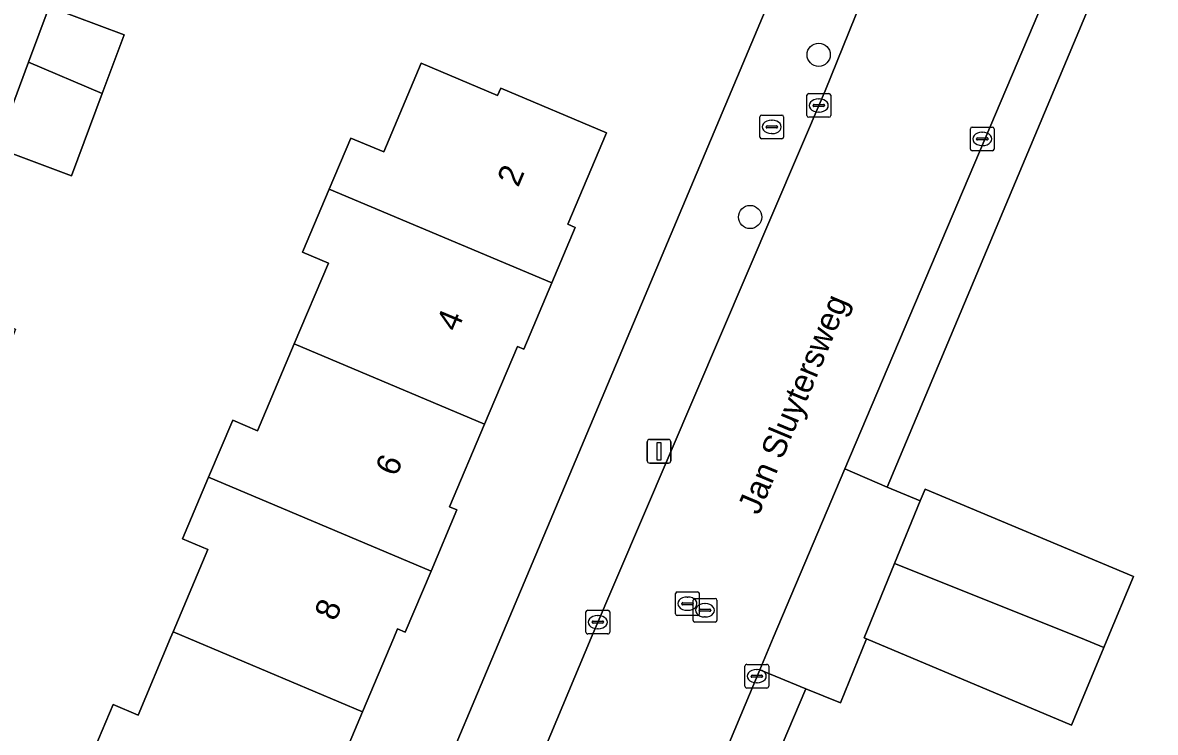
# Model space of a CAD drawing. Extents: x 163266 to 164362, y 381528 to 382286.
# Drawn here: x 163890.27 to 163937.95, y 381996.02 to 382025.91 of the extents above; entities that cross this region are included whole.
import ezdxf

# ---------------------------------------------------------------- set-up
doc = ezdxf.new("R2010")
doc.units = 0
for name, color, linetype in [('IMGEO_Boom', 7, 'Continuous'), ('IMGEO_Brandkraan', 7, 'Continuous'), ('IMGEO_Erf', 7, 'Continuous'), ('IMGEO_Kolk', 7, 'Continuous'), ('IMGEO_Lichtmast', 7, 'Continuous'), ('IMGEO_Openbare_ruimte_label', 7, 'Continuous'), ('IMGEO_Pand', 7, 'Continuous'), ('IMGEO_Pand_nummerreeks', 7, 'Continuous'), ('IMGEO_Rijbaan_lokaal_open', 7, 'Continuous'), ('IMGEO_Rioolput', 7, 'Continuous'), ('IMGEO_Voetpad_open', 7, 'Continuous')]:
    doc.layers.add(name, color=color, linetype=linetype)

msp = doc.modelspace()

# ---------------------------------------------------------------- linework, layer by layer
at = {"layer": 'IMGEO_Boom'}
for centre in [(163923.774, 382024.558), (163920.887, 382017.725)]:
    msp.add_circle(centre, 0.489, dxfattribs=at)
at = {"layer": 'IMGEO_Brandkraan'}
for p, q in [((163921.373, 382022.018), (163922.225, 382022.018)), ((163921.298, 382021.092), (163921.298, 382021.944)), ((163921.557, 382021.512), (163921.557, 382021.524)), ((163921.6, 382021.561), (163921.998, 382021.561)), ((163921.786, 382021.798), (163921.811, 382021.798)), ((163922.041, 382021.524), (163922.041, 382021.512)), ((163922.299, 382021.944), (163922.299, 382021.092)), ((163921.995, 382021.475), (163921.597, 382021.475)), ((163921.809, 382021.238), (163921.784, 382021.238)), ((163922.225, 382021.018), (163921.373, 382021.018))]:
    msp.add_line(p, q, dxfattribs=at)
for points in [[(163921.373, 382022.018), (163922.225, 382022.018)], [(163921.298, 382021.092), (163921.298, 382021.944)], [(163922.299, 382021.944), (163922.299, 382021.092)], [(163922.225, 382021.018), (163921.373, 382021.018)]]:
    msp.add_lwpolyline(points, dxfattribs=at)
for centre, radius, start, end in [((163921.375, 382021.942), 0.0765, 91.552, 178.448), ((163921.375, 382021.942), 0.0765, 91.552, 178.448), ((163922.223, 382021.942), 0.0765, 1.552, 88.448), ((163922.223, 382021.942), 0.0765, 1.552, 88.448), ((163921.597, 382021.521), 0.0403, 85.8775, 175.7526), ((163921.594, 382021.511), 0.0366, 178.938, 274.7102), ((163921.998, 382021.518), 0.043, 264.8664, 352.4533), ((163922.002, 382021.523), 0.0386, 1.7309, 96.639), ((163921.375, 382021.094), 0.0765, 181.552, 268.448), ((163921.375, 382021.094), 0.0765, 181.552, 268.448), ((163922.223, 382021.094), 0.0765, 271.552, 358.448), ((163922.223, 382021.094), 0.0765, 271.552, 358.448)]:
    msp.add_arc(centre, radius, start, end, dxfattribs=at)
for centre, major_axis, ratio, start_param, end_param in [((163921.785, 382021.518), (-0.387, 0.002), 0.722429, 4.712389, 7.853982), ((163921.81, 382021.518), (-0.39, 0.002), 0.717154, 1.570796, 4.712389)]:
    msp.add_ellipse(centre, major_axis=major_axis, ratio=ratio, start_param=start_param, end_param=end_param, dxfattribs=at)
at = {"layer": 'IMGEO_Erf'}
for points in [[(163942.168, 382043.258), (163926.662, 382006.355), (163928.05, 382005.774), (163928.254, 382006.271), (163937.028, 382002.592), (163935.948, 382000), (163935.783, 381999.604), (163934.416, 381996.326), (163925.783, 381999.958), (163924.69, 381997.273), (163923.233, 381997.859), (163913.877, 381975.828)], [(163921.004, 382029.6), (163895.961, 382038.914), (163891.376, 382026.577), (163894.534, 382025.402), (163893.615, 382022.929), (163892.325, 382019.459), (163889.167, 382020.634), (163886.782, 382014.222), (163889.961, 382013.003), (163887.771, 382007.288), (163884.649, 382008.486), (163882.422, 382002.497), (163885.572, 382001.328), (163885.079, 382000), (163884.432, 381998.256), (163883.453, 381995.618), (163880.303, 381996.787), (163876.662, 381986.975), (163899.009, 381979.765)], [(163902.548, 381981.388), (163910.392, 382000), (163921.794, 382027.056)], [(163893.001, 381994.641), (163894.08, 381997.197), (163895.133, 381996.753), (163896.496, 382000), (163896.604, 382000.258), (163898.057, 382003.72), (163896.993, 382004.169), (163898.092, 382006.768), (163899.106, 382009.167), (163900.153, 382008.724), (163901.7, 382012.383), (163903.136, 382015.781), (163902.046, 382016.242), (163903.17, 382018.9), (163904.079, 382021.05), (163905.463, 382020.465), (163907.044, 382024.207), (163910.26, 382022.848), (163910.388, 382023.15), (163914.836, 382021.269), (163913.209, 382017.419), (163913.527, 382017.284), (163912.54, 382014.949), (163911.358, 382012.153), (163911.089, 382012.267), (163909.71, 382009.005), (163908.238, 382005.523), (163908.545, 382005.393), (163907.457, 382002.818), (163906.368, 382000.242), (163906.047, 382000.378), (163905.888, 382000), (163904.578, 381996.894), (163903.111, 381993.415)]]:
    msp.add_lwpolyline(points, dxfattribs=at)
at = {"layer": 'IMGEO_Kolk'}
for p, q in [((163923.278, 382021.997), (163923.278, 382022.849)), ((163923.353, 382022.923), (163924.205, 382022.923)), ((163923.58, 382022.466), (163923.978, 382022.466)), ((163923.766, 382022.703), (163923.791, 382022.703)), ((163924.279, 382022.849), (163924.279, 382021.997)), ((163923.537, 382022.417), (163923.537, 382022.429)), ((163923.975, 382022.38), (163923.577, 382022.38)), ((163923.789, 382022.143), (163923.764, 382022.143)), ((163924.021, 382022.429), (163924.021, 382022.417)), ((163924.205, 382021.923), (163923.353, 382021.923)), ((163930.235, 382021.513), (163931.087, 382021.513)), ((163930.16, 382020.587), (163930.16, 382021.439)), ((163930.462, 382021.056), (163930.86, 382021.056)), ((163930.648, 382021.293), (163930.673, 382021.293)), ((163931.161, 382021.439), (163931.161, 382020.587)), ((163930.419, 382021.007), (163930.419, 382021.019)), ((163930.857, 382020.97), (163930.459, 382020.97)), ((163930.671, 382020.733), (163930.646, 382020.733)), ((163930.903, 382021.019), (163930.903, 382021.007)), ((163931.087, 382020.513), (163930.235, 382020.513)), ((163913.977, 382000.24), (163913.977, 382001.092)), ((163914.052, 382001.166), (163914.904, 382001.166)), ((163914.978, 382001.092), (163914.978, 382000.24)), ((163914.236, 382000.66), (163914.236, 382000.672)), ((163914.674, 382000.623), (163914.276, 382000.623)), ((163914.279, 382000.709), (163914.677, 382000.709)), ((163914.465, 382000.946), (163914.49, 382000.946)), ((163914.72, 382000.672), (163914.72, 382000.66)), ((163914.904, 382000.166), (163914.052, 382000.166)), ((163914.488, 382000.386), (163914.463, 382000.386)), ((163920.668, 381997.962), (163920.668, 381998.814)), ((163920.743, 381998.888), (163921.595, 381998.888)), ((163921.156, 381998.668), (163921.181, 381998.668)), ((163921.669, 381998.814), (163921.669, 381997.962)), ((163920.927, 381998.382), (163920.927, 381998.394)), ((163921.365, 381998.345), (163920.967, 381998.345)), ((163920.97, 381998.431), (163921.368, 381998.431)), ((163921.411, 381998.394), (163921.411, 381998.382)), ((163921.595, 381997.888), (163920.743, 381997.888)), ((163921.179, 381998.108), (163921.154, 381998.108))]:
    msp.add_line(p, q, dxfattribs=at)
for points in [[(163923.278, 382021.997), (163923.278, 382022.849)], [(163923.353, 382022.923), (163924.205, 382022.923)], [(163924.279, 382022.849), (163924.279, 382021.997)], [(163924.205, 382021.923), (163923.353, 382021.923)], [(163930.235, 382021.513), (163931.087, 382021.513)], [(163930.16, 382020.587), (163930.16, 382021.439)], [(163931.161, 382021.439), (163931.161, 382020.587)], [(163931.087, 382020.513), (163930.235, 382020.513)], [(163913.977, 382000.24), (163913.977, 382001.092)], [(163914.052, 382001.166), (163914.904, 382001.166)], [(163914.978, 382001.092), (163914.978, 382000.24)], [(163914.904, 382000.166), (163914.052, 382000.166)], [(163920.668, 381997.962), (163920.668, 381998.814)], [(163920.743, 381998.888), (163921.595, 381998.888)], [(163921.669, 381998.814), (163921.669, 381997.962)], [(163921.595, 381997.888), (163920.743, 381997.888)]]:
    msp.add_lwpolyline(points, dxfattribs=at)
for centre, radius, start, end in [((163923.355, 382022.847), 0.0765, 91.552, 178.448), ((163923.355, 382022.847), 0.0765, 91.552, 178.448), ((163923.577, 382022.426), 0.0403, 85.8775, 175.7526), ((163923.982, 382022.428), 0.0386, 1.7309, 96.639), ((163924.203, 382022.847), 0.0765, 1.552, 88.448), ((163924.203, 382022.847), 0.0765, 1.552, 88.448), ((163923.355, 382021.999), 0.0765, 181.552, 268.448), ((163923.355, 382021.999), 0.0765, 181.552, 268.448), ((163923.574, 382022.416), 0.0366, 178.938, 274.7102), ((163923.978, 382022.423), 0.043, 264.8664, 352.4533), ((163924.203, 382021.999), 0.0765, 271.552, 358.448), ((163924.203, 382021.999), 0.0765, 271.552, 358.448), ((163930.237, 382021.437), 0.0765, 91.552, 178.448), ((163930.237, 382021.437), 0.0765, 91.552, 178.448), ((163931.085, 382021.437), 0.0765, 1.552, 88.448), ((163931.085, 382021.437), 0.0765, 1.552, 88.448), ((163930.459, 382021.016), 0.0403, 85.8775, 175.7526), ((163930.864, 382021.018), 0.0386, 1.7309, 96.639), ((163930.237, 382020.589), 0.0765, 181.552, 268.448), ((163930.237, 382020.589), 0.0765, 181.552, 268.448), ((163930.456, 382021.006), 0.0366, 178.938, 274.7102), ((163930.86, 382021.013), 0.043, 264.8664, 352.4533), ((163931.085, 382020.589), 0.0765, 271.552, 358.448), ((163931.085, 382020.589), 0.0765, 271.552, 358.448), ((163914.054, 382001.09), 0.0765, 91.552, 178.448), ((163914.054, 382001.09), 0.0765, 91.552, 178.448), ((163914.902, 382001.09), 0.0765, 1.552, 88.448), ((163914.902, 382001.09), 0.0765, 1.552, 88.448), ((163914.276, 382000.669), 0.0403, 85.8775, 175.7526), ((163914.273, 382000.659), 0.0366, 178.938, 274.7102), ((163914.677, 382000.666), 0.043, 264.8664, 352.4533), ((163914.681, 382000.671), 0.0386, 1.7309, 96.639), ((163914.054, 382000.242), 0.0765, 181.552, 268.448), ((163914.054, 382000.242), 0.0765, 181.552, 268.448), ((163914.902, 382000.242), 0.0765, 271.552, 358.448), ((163914.902, 382000.242), 0.0765, 271.552, 358.448), ((163920.745, 381998.812), 0.0765, 91.552, 178.448), ((163920.745, 381998.812), 0.0765, 91.552, 178.448), ((163921.593, 381998.812), 0.0765, 1.552, 88.448), ((163921.593, 381998.812), 0.0765, 1.552, 88.448), ((163920.967, 381998.391), 0.0403, 85.8775, 175.7526), ((163920.964, 381998.381), 0.0366, 178.938, 274.7102), ((163921.368, 381998.388), 0.043, 264.8664, 352.4533), ((163921.372, 381998.393), 0.0386, 1.7309, 96.639), ((163920.745, 381997.964), 0.0765, 181.552, 268.448), ((163920.745, 381997.964), 0.0765, 181.552, 268.448), ((163921.593, 381997.964), 0.0765, 271.552, 358.448), ((163921.593, 381997.964), 0.0765, 271.552, 358.448)]:
    msp.add_arc(centre, radius, start, end, dxfattribs=at)
for centre, major_axis, ratio, start_param, end_param in [((163923.765, 382022.423), (-0.387, 0.002), 0.722429, 4.712389, 7.853982), ((163923.79, 382022.423), (-0.39, 0.002), 0.717154, 1.570796, 4.712389), ((163930.647, 382021.013), (-0.387, 0.002), 0.722429, 4.712389, 7.853982), ((163930.672, 382021.013), (-0.39, 0.002), 0.717154, 1.570796, 4.712389), ((163914.464, 382000.666), (-0.387, 0.002), 0.722429, 4.712389, 7.853982), ((163914.489, 382000.666), (-0.39, 0.002), 0.717154, 1.570796, 4.712389), ((163921.155, 381998.388), (-0.387, 0.002), 0.722429, 4.712389, 7.853982), ((163921.18, 381998.388), (-0.39, 0.002), 0.717154, 1.570796, 4.712389)]:
    msp.add_ellipse(centre, major_axis=major_axis, ratio=ratio, start_param=start_param, end_param=end_param, dxfattribs=at)
at = {"layer": 'IMGEO_Lichtmast'}
for p, q in [((163916.56, 382007.461), (163916.56, 382008.261)), ((163916.56, 382008.261), (163916.56, 382007.461)), ((163916.66, 382008.361), (163917.45, 382008.361)), ((163917.45, 382008.361), (163916.66, 382008.361)), ((163917.55, 382008.261), (163917.55, 382007.461)), ((163917.55, 382007.461), (163917.55, 382008.261)), ((163917.45, 382007.361), (163916.66, 382007.361)), ((163916.66, 382007.361), (163917.45, 382007.361))]:
    msp.add_line(p, q, dxfattribs=at)
msp.add_lwpolyline([(163916.98, 382008.236), (163917.13, 382008.236), (163917.13, 382007.486), (163916.98, 382007.486), (163916.98, 382008.236)], dxfattribs=at)
for centre, start, end in [((163916.66, 382008.261), 90, 180), ((163916.66, 382008.261), 90, 180), ((163917.45, 382008.261), 0, 90), ((163917.45, 382008.261), 360, 90), ((163916.66, 382007.461), 180, 270), ((163916.66, 382007.461), 180, 270), ((163917.45, 382007.461), 270, 0), ((163917.45, 382007.461), 270, 0)]:
    msp.add_arc(centre, 0.1, start, end, dxfattribs=at)
at = {"layer": 'IMGEO_Pand'}
for points in [[(163893.615, 382022.929), (163894.534, 382025.402), (163891.376, 382026.577), (163890.507, 382024.239)], [(163893.615, 382022.929), (163890.507, 382024.239), (163889.167, 382020.634), (163892.325, 382019.459)], [(163912.54, 382014.949), (163913.527, 382017.284), (163913.209, 382017.419), (163914.836, 382021.269), (163910.388, 382023.15), (163910.26, 382022.848), (163907.044, 382024.207), (163905.463, 382020.465), (163904.079, 382021.05), (163903.17, 382018.9)], [(163912.54, 382014.949), (163903.17, 382018.9), (163902.046, 382016.242), (163903.136, 382015.781), (163901.7, 382012.383), (163909.71, 382009.005), (163911.089, 382012.267), (163911.358, 382012.153)], [(163898.092, 382006.768), (163907.457, 382002.818), (163908.545, 382005.393), (163908.238, 382005.523), (163909.71, 382009.005), (163901.7, 382012.383), (163900.153, 382008.724), (163899.106, 382009.167)], [(163898.092, 382006.768), (163896.993, 382004.169), (163898.057, 382003.72), (163896.604, 382000.258), (163904.578, 381996.894), (163905.888, 382000), (163906.047, 382000.378), (163906.368, 382000.242), (163907.457, 382002.818)], [(163935.783, 381999.604), (163935.948, 382000), (163937.028, 382002.592), (163928.254, 382006.271), (163928.05, 382005.774), (163926.969, 382003.135), (163934.795, 382000)], [(163935.783, 381999.604), (163934.795, 382000), (163926.969, 382003.135), (163925.684, 382000), (163925.783, 381999.958), (163934.416, 381996.326)], [(163902.391, 381990.68), (163903.48, 381993.259), (163903.111, 381993.415), (163904.578, 381996.894), (163896.604, 382000.258), (163896.496, 382000), (163895.133, 381996.753), (163894.08, 381997.197), (163893.001, 381994.641)]]:
    msp.add_lwpolyline(points, close=True, dxfattribs=at)
at = {"layer": 'IMGEO_Rijbaan_lokaal_open'}
for points in [[(163921.296, 381998.657), (163921.858, 382000), (163924.879, 382007.117), (163940.063, 382042.891), (163935.485, 382044.826), (163935.306, 382044.402), (163934.013, 382041.438)], [(163930.785, 382038.682), (163930.779, 382038.68), (163925.558, 382026.791), (163924.045, 382023.039), (163914.197, 382000), (163906.035, 381980.488)], [(163912.293, 381977.155), (163921.296, 381998.657)]]:
    msp.add_lwpolyline(points, dxfattribs=at)
at = {"layer": 'IMGEO_Rioolput'}
for p, q in [((163917.749, 382001.016), (163917.749, 382001.868)), ((163917.824, 382001.942), (163918.676, 382001.942)), ((163918.051, 382001.485), (163918.449, 382001.485)), ((163918.237, 382001.722), (163918.262, 382001.722)), ((163918.487, 382000.738), (163918.487, 382001.59)), ((163918.562, 382001.664), (163919.414, 382001.664)), ((163918.75, 382001.868), (163918.75, 382001.016)), ((163919.488, 382001.59), (163919.488, 382000.738)), ((163918.008, 382001.436), (163918.008, 382001.448)), ((163918.446, 382001.399), (163918.048, 382001.399)), ((163918.26, 382001.162), (163918.235, 382001.162)), ((163918.492, 382001.448), (163918.492, 382001.436)), ((163918.746, 382001.158), (163918.746, 382001.17)), ((163919.184, 382001.121), (163918.786, 382001.121)), ((163918.789, 382001.207), (163919.187, 382001.207)), ((163918.975, 382001.444), (163919, 382001.444)), ((163919.23, 382001.17), (163919.23, 382001.158)), ((163918.676, 382000.942), (163917.824, 382000.942)), ((163919.414, 382000.664), (163918.562, 382000.664)), ((163918.998, 382000.884), (163918.973, 382000.884))]:
    msp.add_line(p, q, dxfattribs=at)
for points in [[(163917.749, 382001.016), (163917.749, 382001.868)], [(163917.824, 382001.942), (163918.676, 382001.942)], [(163918.487, 382000.738), (163918.487, 382001.59)], [(163918.562, 382001.664), (163919.414, 382001.664)], [(163918.75, 382001.868), (163918.75, 382001.016)], [(163919.488, 382001.59), (163919.488, 382000.738)], [(163918.676, 382000.942), (163917.824, 382000.942)], [(163919.414, 382000.664), (163918.562, 382000.664)]]:
    msp.add_lwpolyline(points, dxfattribs=at)
for centre, radius, start, end in [((163917.826, 382001.866), 0.0765, 91.552, 178.448), ((163917.826, 382001.866), 0.0765, 91.552, 178.448), ((163918.048, 382001.445), 0.0403, 85.8775, 175.7526), ((163918.453, 382001.447), 0.0386, 1.7309, 96.639), ((163918.564, 382001.588), 0.0765, 91.552, 178.448), ((163918.564, 382001.588), 0.0765, 91.552, 178.448), ((163918.674, 382001.866), 0.0765, 1.552, 88.448), ((163918.674, 382001.866), 0.0765, 1.552, 88.448), ((163919.412, 382001.588), 0.0765, 1.552, 88.448), ((163919.412, 382001.588), 0.0765, 1.552, 88.448), ((163917.826, 382001.018), 0.0765, 181.552, 268.448), ((163917.826, 382001.018), 0.0765, 181.552, 268.448), ((163918.045, 382001.435), 0.0366, 178.938, 274.7102), ((163918.449, 382001.442), 0.043, 264.8664, 352.4533), ((163918.674, 382001.018), 0.0765, 271.552, 358.448), ((163918.674, 382001.018), 0.0765, 271.552, 358.448), ((163918.786, 382001.167), 0.0403, 85.8775, 175.7526), ((163918.783, 382001.157), 0.0366, 178.938, 274.7102), ((163919.187, 382001.164), 0.043, 264.8664, 352.4533), ((163919.191, 382001.169), 0.0386, 1.7309, 96.639), ((163918.564, 382000.74), 0.0765, 181.552, 268.448), ((163918.564, 382000.74), 0.0765, 181.552, 268.448), ((163919.412, 382000.74), 0.0765, 271.552, 358.448), ((163919.412, 382000.74), 0.0765, 271.552, 358.448)]:
    msp.add_arc(centre, radius, start, end, dxfattribs=at)
for centre, major_axis, ratio, start_param, end_param in [((163918.236, 382001.442), (-0.387, 0.002), 0.722429, 4.712389, 7.853982), ((163918.261, 382001.442), (-0.39, 0.002), 0.717154, 1.570796, 4.712389), ((163918.974, 382001.164), (-0.387, 0.002), 0.722429, 4.712389, 7.853982), ((163918.999, 382001.164), (-0.39, 0.002), 0.717154, 1.570796, 4.712389)]:
    msp.add_ellipse(centre, major_axis=major_axis, ratio=ratio, start_param=start_param, end_param=end_param, dxfattribs=at)
at = {"layer": 'IMGEO_Voetpad_open'}
for points in [[(163940.349, 382043.565), (163940.063, 382042.891), (163924.879, 382007.117), (163926.662, 382006.355), (163942.168, 382043.258)], [(163924.513, 382032.984), (163921.794, 382027.056), (163910.392, 382000), (163902.548, 381981.388)], [(163924.045, 382023.039), (163925.558, 382026.791)], [(163889.167, 382020.634), (163890.507, 382024.239), (163891.376, 382026.577)], [(163906.035, 381980.488), (163914.197, 382000), (163924.045, 382023.039)], [(163923.233, 381997.859), (163921.296, 381998.657), (163912.293, 381977.155)], [(163913.877, 381975.828), (163923.233, 381997.859)]]:
    msp.add_lwpolyline(points, dxfattribs=at)
msp.add_lwpolyline([(163924.879, 382007.117), (163921.858, 382000), (163921.296, 381998.657), (163923.233, 381997.859), (163924.69, 381997.273), (163925.783, 381999.958), (163925.684, 382000), (163926.969, 382003.135), (163928.05, 382005.774), (163926.662, 382006.355)], close=True, dxfattribs=at)

# ---------------------------------------------------------------- texts
at = {"layer": 'IMGEO_Openbare_ruimte_label'}
msp.add_text('Jan Sluytersweg', height=1, rotation=67.2831, dxfattribs=at).set_placement((163921.254, 382005.138))
at = {"layer": 'IMGEO_Pand_nummerreeks'}
for s, p in [('2', (163911.124, 382018.944)), ('4', (163908.559, 382012.852)), ('6', (163905.995, 382006.759)), ('8', (163903.433, 382000.668))]:
    msp.add_text(s, height=1, rotation=67.1769, dxfattribs=at).set_placement(p)

doc.saveas('drawing.dxf')
